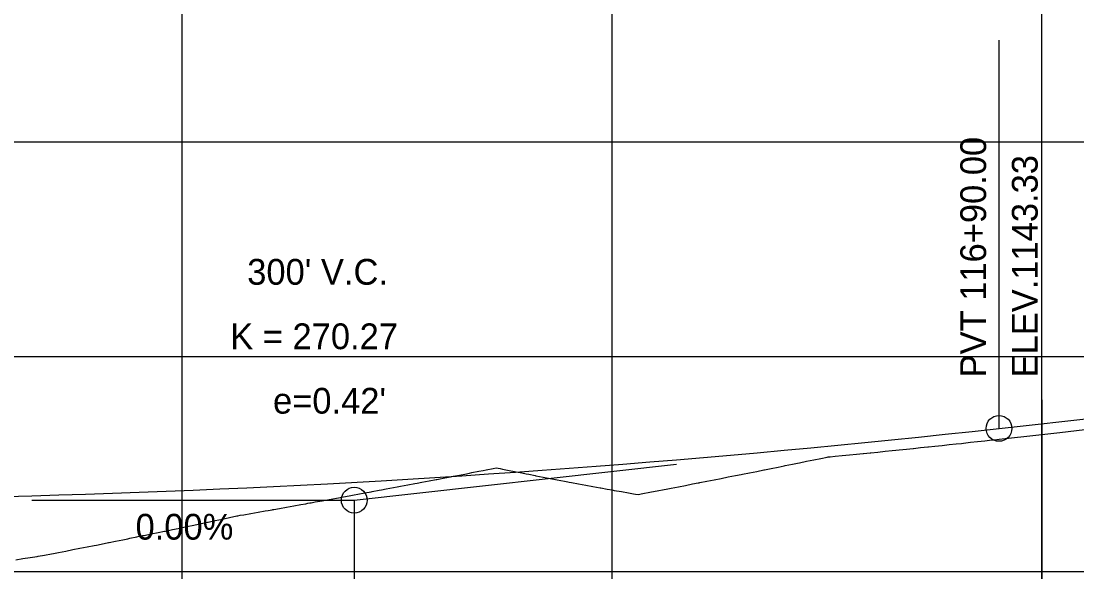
# Model space of a CAD drawing. Extents: x 688474 to 694748, y 765018 to 767373.
# Drawn here: x 692416.1 to 692661.7, y 766059.8 to 766188 of the extents above; entities that cross this region are included whole.
import ezdxf

# ---------------------------------------------------------------- set-up
doc = ezdxf.new("R2010")
doc.units = 0
for name, color, linetype in [('37', 7, 'Continuous'), ('R_No Plot', 7, 'Continuous'), ('R_Profile Work Left', 7, 'Continuous'), ('R_Vert Alg', 7, 'Continuous'), ('R_Vert Alg Annot', 7, 'Continuous')]:
    doc.layers.add(name, color=color, linetype=linetype)

msp = doc.modelspace()

# ---------------------------------------------------------------- linework, layer by layer
at = {"layer": '37'}
for p, q in [((692453.59, 765809.92), (692453.59, 766359.92)), ((692553.59, 765809.92), (692553.59, 766359.92)), ((692653.59, 765809.92), (692653.59, 766359.92)), ((690853.59, 766159.92), (693453.59, 766159.92)), ((690853.59, 766109.92), (693453.59, 766109.92)), ((690853.59, 766059.92), (693453.59, 766059.92))]:
    msp.add_line(p, q, dxfattribs=at)
at = {"layer": 'R_No Plot'}
msp.add_line((692653.59, 766099.88), (692653.59, 765796.18), dxfattribs=at)
at = {"layer": 'R_Profile Work Left'}
msp.add_lwpolyline([(692414.86, 766062.67), (692416.52, 766062.92), (692418.17, 766063.16), (692419.83, 766063.41), (692420.09, 766063.45), (692421.49, 766063.72), (692423.15, 766064.04), (692423.59, 766064.12), (692424.8, 766064.36), (692426.46, 766064.68), (692428.12, 766065), (692429.78, 766065.32), (692431.43, 766065.65), (692433.09, 766065.98), (692433.59, 766066.07), (692434.75, 766066.3), (692436.41, 766066.63), (692436.54, 766066.66), (692438.06, 766066.97), (692439.72, 766067.31), (692440.92, 766067.55), (692441.38, 766067.65), (692443.04, 766067.98), (692443.59, 766068.1), (692444.17, 766068.21), (692444.38, 766068.26), (692444.69, 766068.32), (692446.35, 766068.66), (692448.01, 766069), (692449.46, 766069.3), (692449.67, 766069.34), (692451.32, 766069.68), (692451.79, 766069.78), (692452.98, 766070.03), (692453.59, 766070.16), (692454.64, 766070.37), (692456.3, 766070.72), (692457.95, 766071.07), (692458, 766071.08), (692459.42, 766071.38), (692459.61, 766071.42), (692461.27, 766071.77), (692462.93, 766072.13), (692463.59, 766072.27), (692464.58, 766072.48), (692466.24, 766072.84), (692466.54, 766072.9), (692467.05, 766072.99), (692467.9, 766073.14), (692469.55, 766073.43), (692471.21, 766073.72), (692472.87, 766074.01), (692473.59, 766074.14), (692474.53, 766074.3), (692474.67, 766074.33), (692474.88, 766074.37), (692476.18, 766074.6), (692477.84, 766074.89), (692479.5, 766075.19), (692481.16, 766075.49), (692482.3, 766075.69), (692482.81, 766075.79), (692483.23, 766075.86), (692483.59, 766075.93), (692484.47, 766076.09), (692486.13, 766076.39), (692487.79, 766076.69), (692489.44, 766076.99), (692489.93, 766077.08), (692491.1, 766077.29), (692491.57, 766077.38), (692492.76, 766077.6), (692493.59, 766077.75), (692494.42, 766077.91), (692496.07, 766078.21), (692497.55, 766078.49), (692497.73, 766078.52), (692499.39, 766078.83), (692499.92, 766078.93), (692501.05, 766079.14), (692502.7, 766079.45), (692503.59, 766079.61), (692504.36, 766079.76), (692505.18, 766079.91), (692506.02, 766080.07), (692507.68, 766080.39), (692508.26, 766080.5), (692509.33, 766080.7), (692510.99, 766081.02), (692512.65, 766081.33), (692512.81, 766081.36), (692513.59, 766081.51), (692514.31, 766081.65), (692515.96, 766081.97), (692516.61, 766082.1), (692517.62, 766082.28), (692519.28, 766082.6), (692520.43, 766082.82), (692520.94, 766082.92), (692522.59, 766083.24), (692523.59, 766083.44), (692524.25, 766083.57), (692525.91, 766083.9), (692526.61, 766084.04), (692527.57, 766083.85), (692528.06, 766083.75), (692529.22, 766083.52), (692530.88, 766083.18), (692532.54, 766082.86), (692533.59, 766082.65), (692534.2, 766082.53), (692535.68, 766082.24), (692535.85, 766082.2), (692537.51, 766081.88), (692539.17, 766081.56), (692540.83, 766081.24), (692542.48, 766080.93), (692543.31, 766080.77), (692543.59, 766080.72), (692544.14, 766080.62), (692545.8, 766080.31), (692547.46, 766080), (692549.11, 766079.7), (692550.77, 766079.4), (692550.94, 766079.36), (692552.43, 766079.1), (692553.59, 766078.89), (692554.09, 766078.8), (692555.74, 766078.51), (692557.4, 766078.22), (692558.56, 766078.01), (692559.06, 766077.93), (692559.61, 766077.83), (692560.72, 766078.04), (692562.37, 766078.36), (692563.59, 766078.59), (692564.03, 766078.68), (692565.69, 766079), (692566.19, 766079.09), (692567.35, 766079.31), (692569, 766079.64), (692570.66, 766079.96), (692572.32, 766080.28), (692573.59, 766080.53), (692573.82, 766080.57), (692573.97, 766080.6), (692575.63, 766080.93), (692577.29, 766081.25), (692578.95, 766081.58), (692580.6, 766081.91), (692581.44, 766082.07), (692582.26, 766082.23), (692583.59, 766082.5), (692583.92, 766082.56), (692585.58, 766082.89), (692587.23, 766083.22), (692588.89, 766083.56), (692589.07, 766083.59), (692590.55, 766083.89), (692592.21, 766084.23), (692593.59, 766084.5), (692593.86, 766084.56), (692595.52, 766084.9), (692596.7, 766085.14), (692597.18, 766085.23), (692598.84, 766085.57), (692600.49, 766085.91), (692602.15, 766086.25), (692603.59, 766086.55), (692603.81, 766086.57), (692604.32, 766086.62), (692605.47, 766086.73), (692607.12, 766086.89), (692608.78, 766087.06), (692610.44, 766087.22), (692611.95, 766087.37), (692612.1, 766087.38), (692613.59, 766087.53), (692613.75, 766087.55), (692615.41, 766087.72), (692617.07, 766087.88), (692618.73, 766088.05), (692619.58, 766088.14), (692620.38, 766088.22), (692622.04, 766088.39), (692623.59, 766088.55), (692623.7, 766088.56), (692625.36, 766088.74), (692627.01, 766088.91), (692627.2, 766088.93), (692628.67, 766089.09), (692630.33, 766089.26), (692631.99, 766089.44), (692633.59, 766089.61), (692633.64, 766089.62), (692634.83, 766089.74), (692635.3, 766089.8), (692636.96, 766089.98), (692638.62, 766090.16), (692640.27, 766090.34), (692641.93, 766090.52), (692642.46, 766090.58), (692643.59, 766090.71), (692650.08, 766091.43), (692653.59, 766091.82), (692657.71, 766092.28), (692663.59, 766092.93)], dxfattribs=at)
at = {"layer": 'R_Vert Alg'}
for p, q in [((692643.59, 766093.22), (692899.77, 766121.72)), ((692493.59, 766076.52), (692568.59, 766084.87)), ((692418.59, 766076.52), (692493.59, 766076.52))]:
    msp.add_line(p, q, dxfattribs=at)
msp.add_lwpolyline([(692412.34, 766077.4), (692418.59, 766077.56), (692424.84, 766077.74), (692431.09, 766077.94), (692437.34, 766078.15), (692443.59, 766078.38), (692449.84, 766078.61), (692456.09, 766078.87), (692462.34, 766079.14), (692468.59, 766079.42), (692474.84, 766079.72), (692481.09, 766080.03), (692487.34, 766080.35), (692499.84, 766081.05), (692506.09, 766081.42), (692512.34, 766081.8), (692518.59, 766082.2), (692524.84, 766082.61), (692531.09, 766083.04), (692537.34, 766083.48), (692543.59, 766083.94), (692549.84, 766084.41), (692556.09, 766084.9), (692562.34, 766085.4), (692568.59, 766085.91), (692574.84, 766086.44), (692581.09, 766086.98), (692587.34, 766087.54), (692593.59, 766088.12), (692599.84, 766088.7), (692606.09, 766089.3), (692612.34, 766089.92), (692618.59, 766090.55), (692624.84, 766091.2), (692631.09, 766091.85), (692637.34, 766092.53), (692643.59, 766093.22)], dxfattribs=at)
for centre in [(692643.59, 766093.22), (692493.59, 766076.52)]:
    msp.add_circle(centre, 3, dxfattribs=at)
at = {"layer": 'R_Vert Alg Annot'}
for p, q in [((692643.59, 766093.22), (692643.59, 766183.53)), ((692493.59, 766076.52), (692493.59, 765940.34))]:
    msp.add_line(p, q, dxfattribs=at)

# ---------------------------------------------------------------- texts
for s, rotation, p in [('PVT 116+90.00', 90, (692640.59, 766105.08)), ('ELEV.1143.33', 90, (692652.59, 766105.08)), ('0.00%', 360, (692442.71, 766067.33))]:
    msp.add_text(s, height=6, rotation=rotation, dxfattribs=at).set_placement(p)
for s, p in [("300' V.C.", (692468.69, 766126.65)), ('K = 270.27', (692464.73, 766111.65)), ("e=0.42'", (692474.69, 766096.65))]:
    msp.add_text(s, height=6, dxfattribs=at).set_placement(p)

doc.saveas('drawing.dxf')
